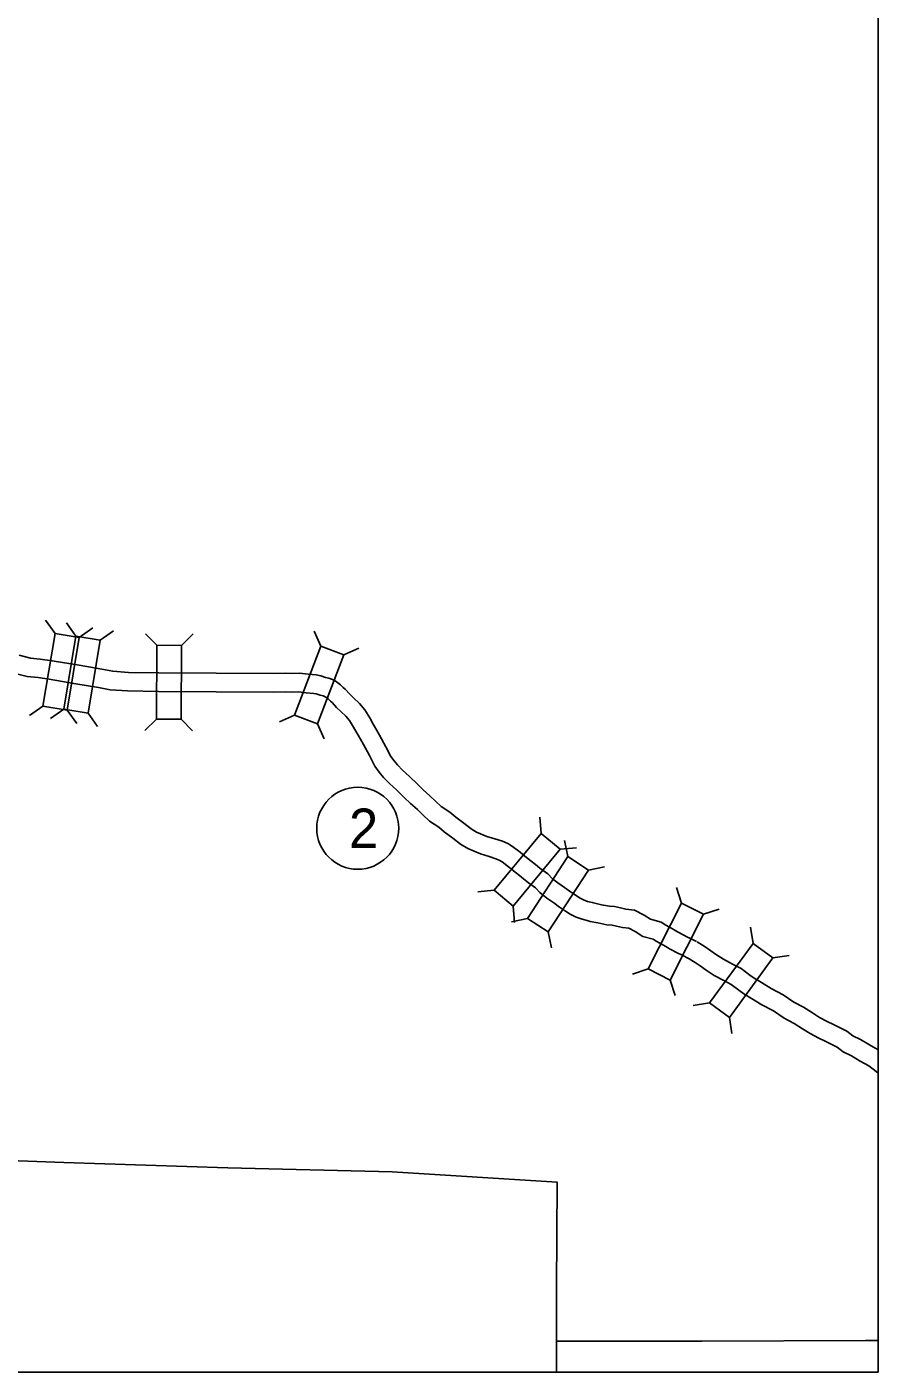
# Model space of a CAD drawing. Extents: x 1382482 to 1385815, y 1168351 to 1170484.
# Drawn here: x 1383234.6 to 1383371.6, y 1169604.3 to 1169820.9 of the extents above; entities that cross this region are included whole.
import ezdxf

# ---------------------------------------------------------------- set-up
doc = ezdxf.new("R2010")
doc.units = 0
for name, color, linetype in [('15', 7, 'Continuous'), ('2', 7, 'Continuous'), ('20', 7, 'Continuous'), ('Default', 7, 'Continuous'), ('R_No Plot', 7, 'Continuous')]:
    doc.layers.add(name, color=color, linetype=linetype)

msp = doc.modelspace()

# ---------------------------------------------------------------- linework, layer by layer
at = {"layer": '15'}
for points in [[(1383342.39, 1169673.59), (1383341.62, 1169674), (1383341.29, 1169674.14), (1383340.96, 1169674.31), (1383339.53, 1169675.04), (1383339.3, 1169675.18), (1383338.53, 1169675.65), (1383337.42, 1169676.22), (1383336.72, 1169676.71), (1383335, 1169677.2), (1383333.98, 1169677.84), (1383332.38, 1169678.66), (1383331, 1169678.83), (1383330.13, 1169679.04), (1383329.18, 1169679.22), (1383328.38, 1169679.28), (1383327.1, 1169679.54), (1383326.03, 1169679.76), (1383325.59, 1169679.9), (1383324.85, 1169680.07), (1383324.19, 1169680.32), (1383323.52, 1169680.62), (1383323.01, 1169680.99), (1383322.07, 1169681.61), (1383321.13, 1169682.32), (1383320.04, 1169683.03), (1383319.19, 1169683.69), (1383318.46, 1169684.49), (1383317.16, 1169685.42), (1383316.45, 1169686), (1383315.79, 1169686.54), (1383315.02, 1169687.15), (1383314.43, 1169687.61), (1383314.01, 1169687.98), (1383312.78, 1169688.89), (1383312, 1169689.38), (1383311.14, 1169689.74), (1383309.91, 1169690.16), (1383308.6, 1169690.53), (1383306.96, 1169691.22), (1383306.11, 1169691.76), (1383304.93, 1169692.67), (1383303.61, 1169693.63), (1383302.68, 1169694.41), (1383301.28, 1169695.35), (1383300.37, 1169696.19), (1383299.47, 1169697.06), (1383298.36, 1169698.01), (1383297.44, 1169698.94), (1383296.19, 1169700.16), (1383295.02, 1169701.21), (1383294.22, 1169702.04), (1383293.68, 1169702.7), (1383293.16, 1169703.41), (1383292.38, 1169704.97), (1383291.36, 1169706.82), (1383290.86, 1169707.68), (1383290.34, 1169708.6), (1383289.76, 1169709.62), (1383288.97, 1169710.92), (1383288.13, 1169711.94), (1383287.17, 1169712.85), (1383286.54, 1169713.41), (1383285.82, 1169714.21), (1383285.47, 1169714.52), (1383285.04, 1169714.95), (1383284.42, 1169715.4), (1383284.02, 1169715.66), (1383283.16, 1169716.01), (1383282.63, 1169716.13), (1383281.92, 1169716.4), (1383281.14, 1169716.52), (1383279.87, 1169716.63), (1383278.52, 1169716.81), (1383277.27, 1169716.77), (1383276.19, 1169716.81), (1383274.3, 1169716.75), (1383255.81, 1169716.86), (1383250.91, 1169716.93), (1383248.38, 1169717.13), (1383246.61, 1169717.47), (1383242.97, 1169718.08), (1383238.63, 1169718.8), (1383236.72, 1169719.08), (1383235.14, 1169719.23), (1383233.34, 1169719.69)], [(1383341, 1169670.93), (1383340.31, 1169671.3), (1383340, 1169671.44), (1383339.6, 1169671.64), (1383338.06, 1169672.42), (1383337.73, 1169672.62), (1383337.06, 1169673.03), (1383335.87, 1169673.64), (1383335.41, 1169673.96), (1383333.77, 1169674.43), (1383332.5, 1169675.23), (1383331.49, 1169675.74), (1383330.47, 1169675.87), (1383329.5, 1169676.1), (1383328.78, 1169676.24), (1383327.96, 1169676.3), (1383326.5, 1169676.6), (1383325.27, 1169676.85), (1383324.8, 1169677), (1383323.96, 1169677.2), (1383323.03, 1169677.55), (1383322.03, 1169678.01), (1383321.31, 1169678.52), (1383320.34, 1169679.16), (1383319.41, 1169679.86), (1383318.29, 1169680.59), (1383317.14, 1169681.49), (1383316.46, 1169682.24), (1383315.35, 1169683.03), (1383314.54, 1169683.68), (1383313.9, 1169684.21), (1383313.17, 1169684.79), (1383312.53, 1169685.29), (1383312.12, 1169685.65), (1383311.09, 1169686.41), (1383310.62, 1169686.71), (1383310.08, 1169686.94), (1383309.02, 1169687.3), (1383307.6, 1169687.7), (1383305.56, 1169688.56), (1383304.39, 1169689.3), (1383303.13, 1169690.27), (1383301.76, 1169691.26), (1383300.87, 1169692.01), (1383299.42, 1169692.99), (1383298.32, 1169694), (1383297.45, 1169694.84), (1383296.31, 1169695.81), (1383295.32, 1169696.82), (1383294.13, 1169697.97), (1383292.94, 1169699.06), (1383291.99, 1169700.04), (1383291.31, 1169700.86), (1383290.59, 1169701.84), (1383289.72, 1169703.57), (1383288.75, 1169705.34), (1383288.26, 1169706.19), (1383287.73, 1169707.12), (1383287.17, 1169708.1), (1383286.52, 1169709.18), (1383285.93, 1169709.89), (1383285.14, 1169710.63), (1383284.42, 1169711.28), (1383283.71, 1169712.07), (1383283.43, 1169712.32), (1383283.09, 1169712.66), (1383282.72, 1169712.93), (1383282.61, 1169712.99), (1383282.26, 1169713.14), (1383281.77, 1169713.25), (1383281.14, 1169713.49), (1383280.78, 1169713.54), (1383279.54, 1169713.65), (1383278.37, 1169713.81), (1383277.27, 1169713.77), (1383276.17, 1169713.81), (1383274.33, 1169713.75), (1383255.77, 1169713.86), (1383250.77, 1169713.94), (1383247.98, 1169714.15), (1383246.08, 1169714.52), (1383242.47, 1169715.12), (1383238.16, 1169715.84), (1383236.37, 1169716.1), (1383234.63, 1169716.26), (1383232.66, 1169716.77)], [(1383371.62, 1169656.18), (1383370.26, 1169656.95), (1383368.77, 1169657.83), (1383367.58, 1169658.41), (1383366.61, 1169659.15), (1383364.43, 1169660.26), (1383363.44, 1169660.74), (1383362.17, 1169661.4), (1383361.04, 1169662.1), (1383359.61, 1169663.03), (1383358.03, 1169663.82), (1383356.35, 1169665.02), (1383354.4, 1169666.04), (1383352.83, 1169666.99), (1383351.69, 1169667.7), (1383350.96, 1169668.2), (1383349.55, 1169669.24), (1383348.19, 1169669.97), (1383346.75, 1169670.76), (1383345.61, 1169671.46), (1383344.71, 1169672.13), (1383343.76, 1169672.77), (1383342.49, 1169673.54)], [(1383371.62, 1169652.39), (1383371.32, 1169652.66), (1383370.11, 1169653.59), (1383368.76, 1169654.35), (1383367.34, 1169655.19), (1383366, 1169655.85), (1383365.01, 1169656.59), (1383363.09, 1169657.57), (1383362.1, 1169658.06), (1383360.69, 1169658.79), (1383359.43, 1169659.56), (1383358.12, 1169660.42), (1383356.48, 1169661.25), (1383354.78, 1169662.45), (1383352.93, 1169663.42), (1383351.26, 1169664.43), (1383350.03, 1169665.2), (1383349.22, 1169665.76), (1383347.94, 1169666.7), (1383346.76, 1169667.34), (1383345.25, 1169668.16), (1383343.92, 1169668.97), (1383342.97, 1169669.68), (1383342.15, 1169670.24), (1383340.91, 1169670.98), (1383340.9, 1169670.99)]]:
    msp.add_lwpolyline(points, dxfattribs=at)
at = {"layer": '2'}
for points in [[(1383214.29, 1169639.02), (1383240.52, 1169638.01), (1383266.94, 1169637.15), (1383293.38, 1169636.5), (1383319.95, 1169634.84), (1383319.86, 1169617.82)], [(1383319.83, 1169609.24), (1383319.86, 1169617.82)], [(1383371.62, 1169609.38), (1383369.57, 1169609.38), (1383343.25, 1169609.29), (1383319.83, 1169609.24), (1383319.82, 1169604.28)]]:
    msp.add_lwpolyline(points, dxfattribs=at)
at = {"layer": '20'}
for p, q in [((1383239.1, 1169723.22), (1383237.57, 1169725.37)), ((1383242.45, 1169722.76), (1383240.92, 1169724.91)), ((1383243.01, 1169722.57), (1383245.16, 1169724.11)), ((1383246.36, 1169722.11), (1383248.51, 1169723.64)), ((1383255.51, 1169721.3), (1383253.66, 1169723.17)), ((1383259.47, 1169721.28), (1383261.35, 1169723.13)), ((1383281.88, 1169721.17), (1383280.81, 1169723.58)), ((1383242.45, 1169722.76), (1383242.45, 1169722.76)), ((1383285.58, 1169719.75), (1383287.99, 1169720.83)), ((1383237.15, 1169711.5), (1383235, 1169709.97)), ((1383240.5, 1169711.04), (1383238.35, 1169709.5)), ((1383241.05, 1169710.85), (1383242.59, 1169708.71)), ((1383244.41, 1169710.39), (1383245.94, 1169708.24)), ((1383277.64, 1169710.07), (1383275.23, 1169709)), ((1383255.45, 1169709.42), (1383253.57, 1169707.56)), ((1383259.41, 1169709.4), (1383261.26, 1169707.52)), ((1383281.34, 1169708.66), (1383282.41, 1169706.25)), ((1383317.38, 1169690.99), (1383317.14, 1169693.62)), ((1383320.43, 1169688.46), (1383323.06, 1169688.71)), ((1383321.67, 1169687.27), (1383321.13, 1169689.85)), ((1383324.99, 1169685.1), (1383327.57, 1169685.64)), ((1383309.8, 1169681.85), (1383307.17, 1169681.6)), ((1383339.99, 1169679.78), (1383339.17, 1169682.29)), ((1383312.85, 1169679.32), (1383313.09, 1169676.69)), ((1383343.52, 1169677.99), (1383346.03, 1169678.81)), ((1383315.17, 1169677.32), (1383312.59, 1169676.78)), ((1383351.5, 1169673.31), (1383351.1, 1169675.92)), ((1383318.49, 1169675.15), (1383319.03, 1169672.57)), ((1383354.7, 1169670.97), (1383357.31, 1169671.38)), ((1383334.61, 1169669.19), (1383332.1, 1169668.37)), ((1383338.14, 1169667.4), (1383338.96, 1169664.89)), ((1383344.48, 1169663.73), (1383341.87, 1169663.32)), ((1383347.68, 1169661.39), (1383348.08, 1169658.78))]:
    msp.add_line(p, q, dxfattribs=at)
for points in [[(1383241.05, 1169710.85), (1383243.01, 1169722.57), (1383239.1, 1169723.22), (1383237.15, 1169711.5)], [(1383242.45, 1169722.76), (1383240.5, 1169711.04), (1383244.41, 1169710.39), (1383246.36, 1169722.11)], [(1383259.41, 1169709.4), (1383259.47, 1169721.28), (1383255.51, 1169721.3), (1383255.45, 1169709.42)], [(1383281.34, 1169708.66), (1383285.58, 1169719.75), (1383281.88, 1169721.17), (1383277.64, 1169710.07)], [(1383312.85, 1169679.32), (1383320.43, 1169688.46), (1383317.38, 1169690.99), (1383309.8, 1169681.85)], [(1383321.67, 1169687.27), (1383315.17, 1169677.32), (1383318.49, 1169675.15), (1383324.99, 1169685.1)], [(1383338.14, 1169667.4), (1383343.52, 1169677.99), (1383339.99, 1169679.78), (1383334.61, 1169669.19)], [(1383351.5, 1169673.31), (1383344.48, 1169663.73), (1383347.68, 1169661.39), (1383354.7, 1169670.97)]]:
    msp.add_lwpolyline(points, close=True, dxfattribs=at)
at = {"layer": 'Default'}
msp.add_circle((1383287.84, 1169691.84), 6.6, dxfattribs=at)
at = {"layer": 'R_No Plot'}
msp.add_lwpolyline([(1382642.23, 1170388.77), (1383371.62, 1170388.77), (1383371.62, 1169604.28), (1382642.23, 1169604.28)], close=True, dxfattribs=at)

# ---------------------------------------------------------------- texts
at = {"layer": 'Default'}
msp.add_text('2', height=6.34, dxfattribs=at).set_placement((1383286.42, 1169688.67))

doc.saveas('drawing.dxf')
